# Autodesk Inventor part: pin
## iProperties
Author: GJOHNST2
Shininess: 20.0
Length Units: 11272
Angle Units: 11286
Time Units: 11279
Mass Units: 11290
Length Display Precision: 3
Angle Display Precision: 2
Compacted: True
PropertySet Name: _Private Model Information
Created: 2001-12
Part Number: pin
Document SubType Name: Modeling
Designer: GJOHNST2
Control State: 0
Master: False
Checked Out: False
PropertySet Name: Design Tracking Control
Density: 0.0
Volumn: 0.0
Area: 0.0
PropertySet Name: Model Information
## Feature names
1. Extrusion1
2. Extrusion2
3. Fillet1
4. Extrusion3
5. Fillet2
